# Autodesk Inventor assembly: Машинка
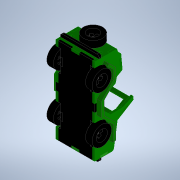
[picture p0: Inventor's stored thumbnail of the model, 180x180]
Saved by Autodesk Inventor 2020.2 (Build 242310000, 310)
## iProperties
Created: 2020-04
Part Number: Машинка
Document SubType Name: Assembly
Designer: Алексей
Author: Алексей
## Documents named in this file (19)
- C:\Users\Алексей\Desktop\Машинка\Машинка.iam
- C:\Users\Алексей\Desktop\Машинка\Бок.ipt
- C:\Users\Алексей\Desktop\Машинка\Низ1.ipt
- C:\Users\Алексей\Desktop\Машинка\перед.ipt
- C:\Users\Алексей\Desktop\Машинка\Зад.ipt
- C:\Users\Алексей\Desktop\Машинка\Стекло.ipt
- C:\Users\Алексей\Desktop\Машинка\капот.ipt
- C:\Users\Алексей\Desktop\Машинка\багажник.ipt
- C:\Users\Алексей\Desktop\Машинка\Колесо1.ipt
- C:\Users\Алексей\Desktop\Машинка\бампер передний.ipt
- C:\Users\Алексей\Desktop\Машинка\рама1.ipt
- C:\Users\Алексей\Desktop\Машинка\крыло.ipt
- C:\Users\Алексей\Desktop\Машинка\рама2.ipt
- C:\Users\Алексей\Desktop\Машинка\дверь.ipt
- C:\Users\Алексей\Desktop\Машинка\крыло_ЗЕРКАЛО.ipt
- C:\Users\Алексей\Desktop\Машинка\шайба.ipt
- C:\Users\Алексей\Desktop\Машинка\шайба_ЗЕРКАЛО.ipt
- C:\Users\Алексей\Desktop\Машинка\Вал.ipt
- C:\Users\Алексей\Desktop\Машинка\втулка.ipt
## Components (29 placed, 18 different names)
1. Бок:1 — Заподлицо:1, Заподлицо:2, Заподлицо:4, Жесткий:5
2. Низ1:1 — Заподлицо:1, Жесткий:1, Заподлицо:10, Жесткий:2, Совмещение:1, Угол:1
3. Бок:2 — Жесткий:1, Заподлицо:3, Заподлицо:5, Заподлицо:6, Заподлицо:11, Заподлицо:13
4. перед:1 — Заподлицо:2, Заподлицо:9
5. Зад:1 — Заподлицо:3, Заподлицо:7, Жесткий:3, Заподлицо:16
6. Стекло:1 — Заподлицо:4
7. капот:1 — Заподлицо:5
8. багажник:1 — Заподлицо:6
9. Колесо1:1 — Заподлицо:7, С поворотом:5
10. бампер передний:1 — Заподлицо:9
11. бампер передний:2 — Жесткий:3
12. рама1:1 — Заподлицо:10, С поворотом:2, С поворотом:3
13. рама1:2 — Жесткий:2, Заподлицо:12, Жесткий:4, Заподлицо:14, С поворотом:1, С поворотом:9
14. крыло:1 — Заподлицо:11
15. рама2:1 — Заподлицо:12
16. рама2:3 — Жесткий:4
17. дверь:1 — Заподлицо:13
18. крыло_ЗЕРКАЛО:1 — Жесткий:5
19. шайба:1 — Заподлицо:14
20. шайба:2 — С поворотом:1, С поворотом:9, Жесткий:6
21. шайба_ЗЕРКАЛО:1 — С поворотом:3, Жесткий:7
22. шайба_ЗЕРКАЛО:2 — С поворотом:2, Заподлицо:15, С поворотом:10
23. втулка:1 — Заподлицо:16, С поворотом:5
24. Колесо1:4 — Жесткий:6
25. Колесо1:5 — С поворотом:7
26. Колесо1:6 — Жесткий:7
27. Колесо1:7 — С поворотом:10
28. Вал:1 — Заподлицо:15
29. Вал:2 — С поворотом:7
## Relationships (31: Flush 15, WeldJoint 7, RevoluteJoint 7, Mate 1, Angle 1)
- Заподлицо:1 [Flush]: Бок:1 ↔ Низ1:1
- Жесткий:1 [WeldJoint]: Низ1:1 ↔ Бок:2
- Заподлицо:2 [Flush]: Бок:1 ↔ перед:1
- Заподлицо:3 [Flush]: Бок:2 ↔ Зад:1
- Заподлицо:4 [Flush]: Бок:1 ↔ Стекло:1
- Заподлицо:5 [Flush]: Бок:2 ↔ капот:1
- Заподлицо:6 [Flush]: Бок:2 ↔ багажник:1
- Заподлицо:7 [Flush]: Зад:1 ↔ Колесо1:1
- Заподлицо:9 [Flush]: перед:1 ↔ бампер передний:1
- Заподлицо:10 [Flush]: Низ1:1 ↔ рама1:1
- Жесткий:2 [WeldJoint]: Низ1:1 ↔ рама1:2
- Жесткий:3 [WeldJoint]: Зад:1 ↔ бампер передний:2
- Заподлицо:11 [Flush]: Бок:2 ↔ крыло:1
- Заподлицо:12 [Flush]: рама1:2 ↔ рама2:1
- Заподлицо:13 [Flush]: Бок:2 ↔ дверь:1
- Жесткий:4 [WeldJoint]: рама1:2 ↔ рама2:3
- Жесткий:5 [WeldJoint]: Бок:1 ↔ крыло_ЗЕРКАЛО:1
- Заподлицо:14 [Flush]: рама1:2 ↔ шайба:1
- С поворотом:1 [RevoluteJoint]: рама1:2 ↔ шайба:2
- С поворотом:2 [RevoluteJoint]: рама1:1 ↔ шайба_ЗЕРКАЛО:2
- С поворотом:3 [RevoluteJoint]: рама1:1 ↔ шайба_ЗЕРКАЛО:1
- Заподлицо:15 [Flush]: шайба_ЗЕРКАЛО:2 ↔ Вал:1
- Совмещение:1 [Mate]: Низ1:1
- Угол:1 [Angle]: Низ1:1
- Заподлицо:16 [Flush]: Зад:1 ↔ втулка:1
- С поворотом:5 [RevoluteJoint]: Колесо1:1 ↔ втулка:1
- С поворотом:7 [RevoluteJoint]: Колесо1:5 ↔ Вал:2
- С поворотом:9 [RevoluteJoint]: рама1:2 ↔ шайба:2
- Жесткий:6 [WeldJoint]: шайба:2 ↔ Колесо1:4
- Жесткий:7 [WeldJoint]: шайба_ЗЕРКАЛО:1 ↔ Колесо1:6
- С поворотом:10 [RevoluteJoint]: шайба_ЗЕРКАЛО:2 ↔ Колесо1:7
